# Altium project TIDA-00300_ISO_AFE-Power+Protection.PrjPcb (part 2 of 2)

## Sheet TIDA-00300_ISO_AFE-Power+Protection _Pg5.SchDoc: ISOLATED AFE SUPPLY , LDOs
size 431 x 279 mm; Date: Not shown in title block; ApprovedBy: Not shown in title block; CheckedBy: Not shown in title block; Author: Not shown in title block; CompanyName: Not shown in title block; DrawnBy: Sreenivasa; Engineer: Not shown in title block; Organization: Not shown in title block; Address1: Not shown in title block; Address2: Not shown in title block; Address3: Not shown in title block; Address4: Not shown in title block; DocumentNumber: 1; Revision: Use project parameter SCH_Rev; SheetNumber: 5; SheetTotal: 6; PageSetup: Record=PageOptions¦CenterHorizontal=True¦CenterVertical=True¦PrintScale=0.62¦XCorrection=1.00¦YCorrection=1.00¦PrintKind=0¦BorderSize=5000000¦LeftOffset=0¦BottomOffset=0¦Orientation=2¦PaperLength=1000¦PaperWidth=1000¦Scale=100¦PaperSource=15¦PrintQuality=600¦MediaType=1¦DitherType=10¦PrintScaleMode=1¦PaperKind=Letter
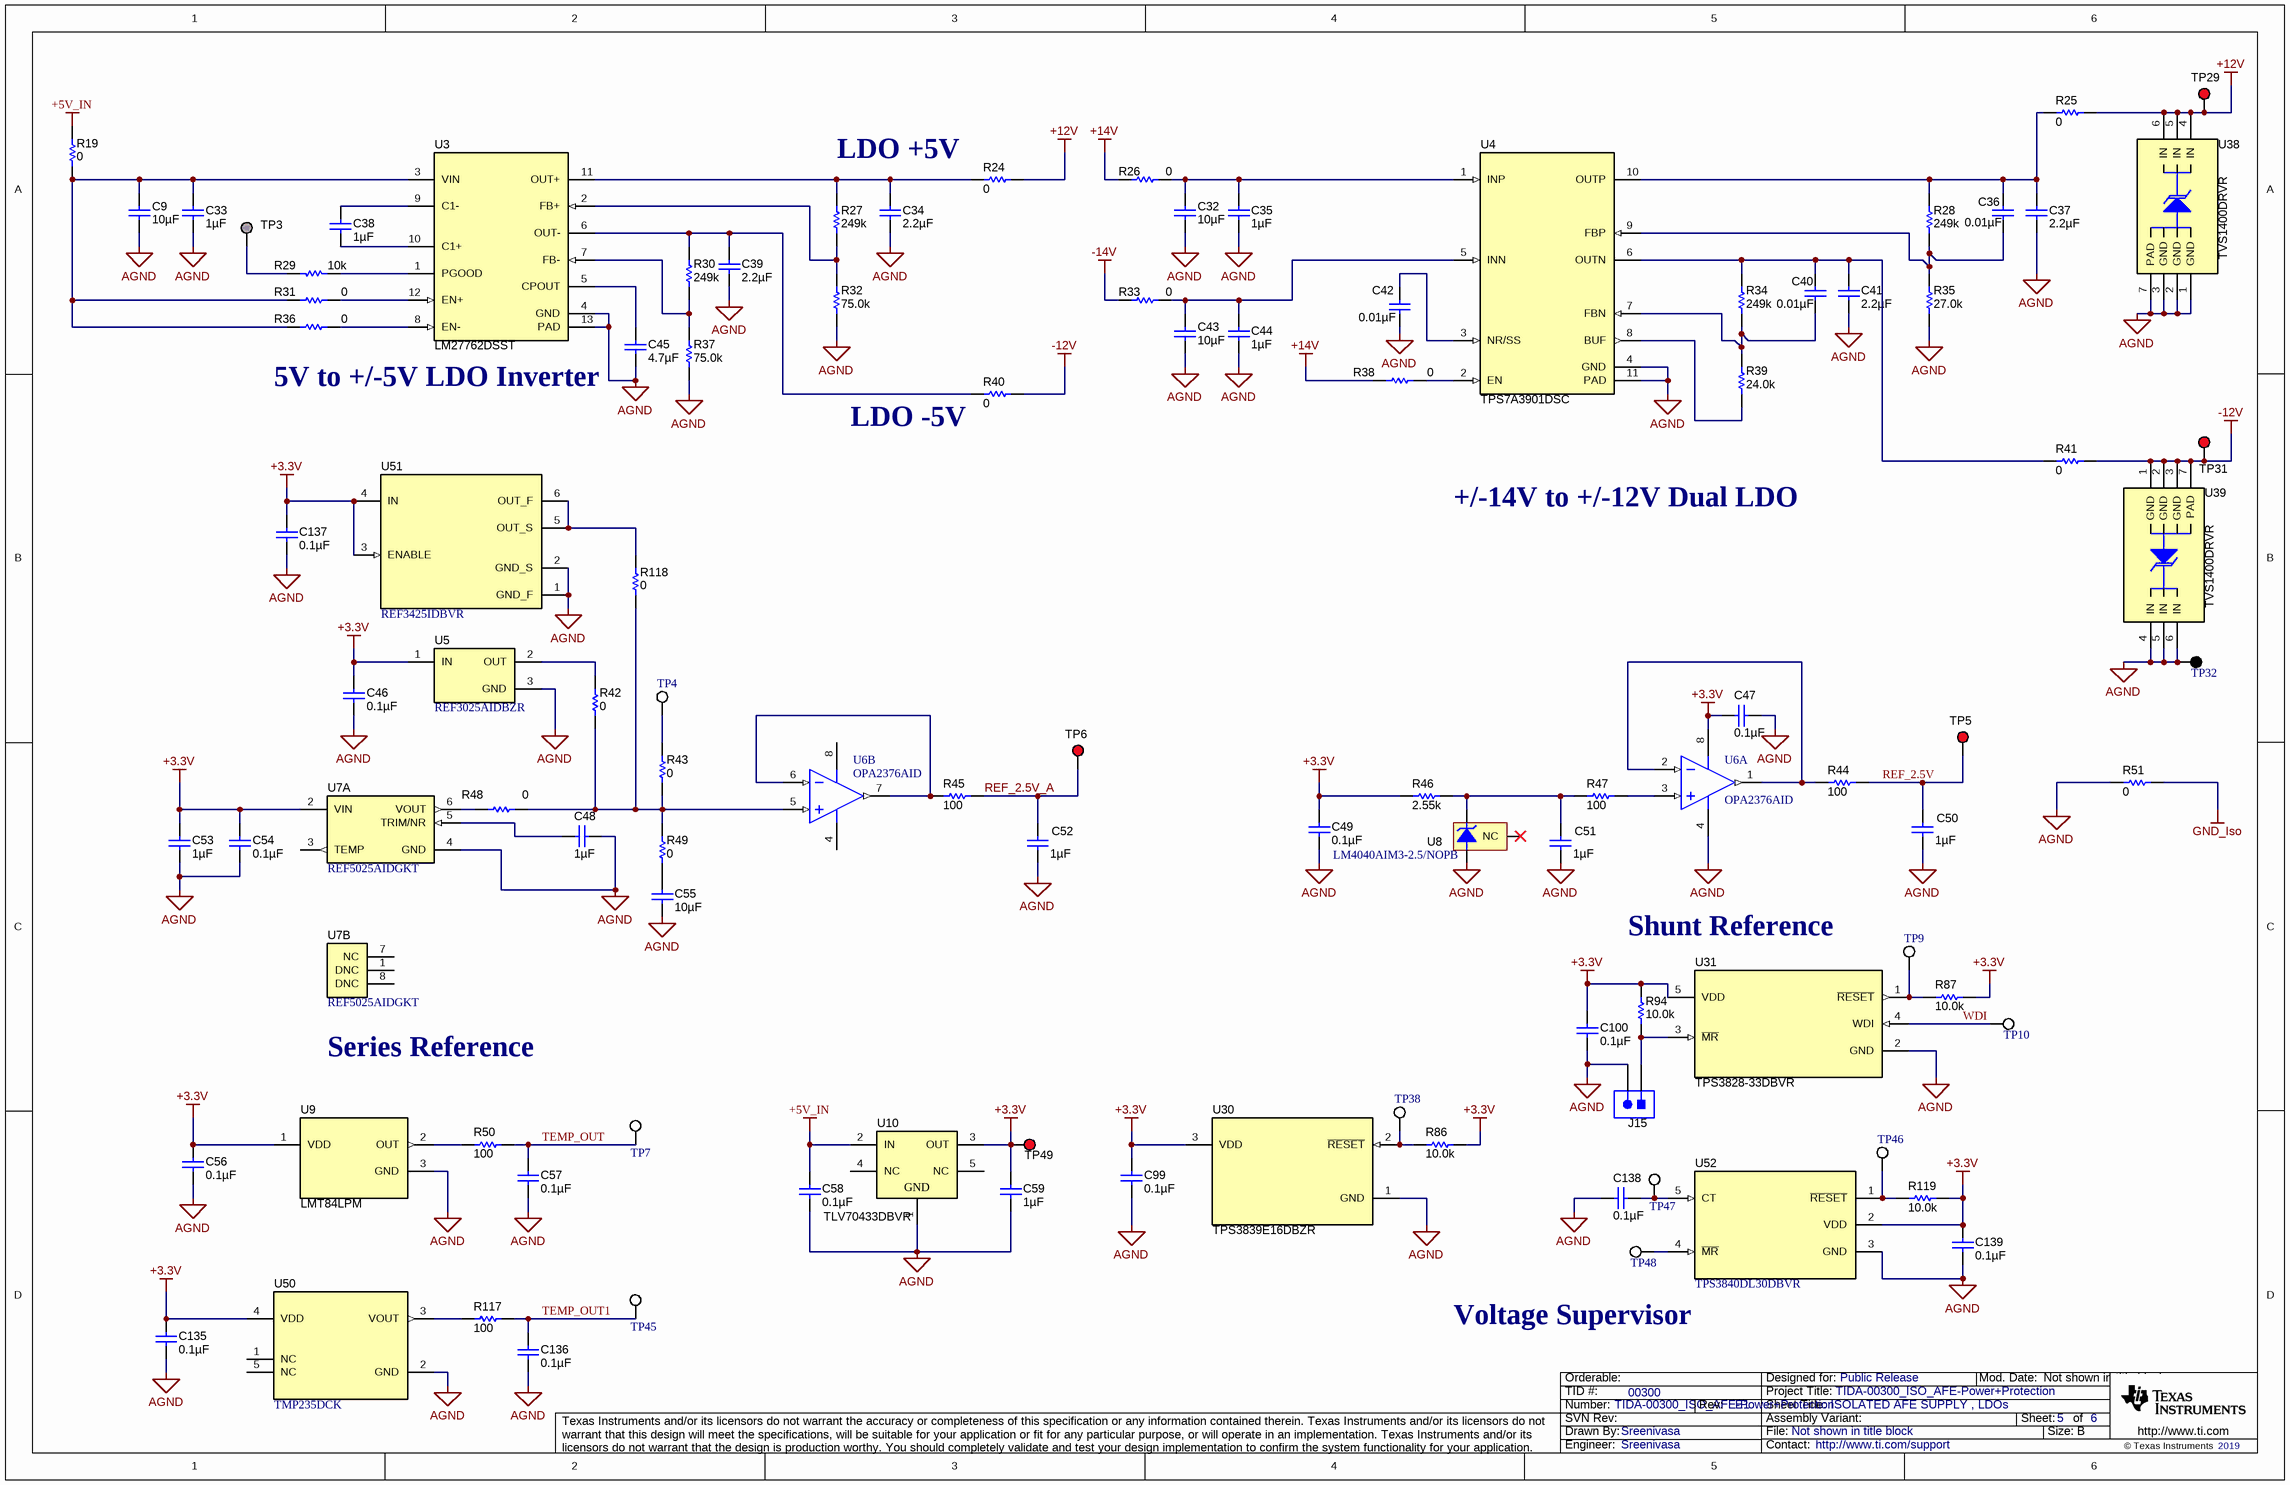
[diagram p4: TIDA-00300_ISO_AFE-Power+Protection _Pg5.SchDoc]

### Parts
C9  ValueDisplayed: 10µF  [1210]
C32  ValueDisplayed: 10µF  [1210]
C33  ValueDisplayed: 1µF  [0603S]  (hidden comment: CGA3E1X7R1E105K080AC)
C34  ValueDisplayed: 2.2µF  [0805_HV]  (hidden comment: C0805C225K8RACTU)
C35  ValueDisplayed: 1µF  [0603S]  (hidden comment: CGA3E1X7R1E105K080AC)
C36  ValueDisplayed: 0.01µF  [0603]  (hidden comment: 885012206040)
C37  ValueDisplayed: 2.2µF  [0805_HV]  (hidden comment: C0805C225K8RACTU)
C38  ValueDisplayed: 1µF  [0603S]  (hidden comment: CGA3E1X7R1E105K080AC)
C39  ValueDisplayed: 2.2µF  [0805_HV]  (hidden comment: C0805C225K8RACTU)
C40  ValueDisplayed: 0.01µF  [0603]  (hidden comment: 885012206040)
C41  ValueDisplayed: 2.2µF  [0805_HV]  (hidden comment: C0805C225K8RACTU)
C42  ValueDisplayed: 0.01µF  [0603]  (hidden comment: 885012206040)
C43  ValueDisplayed: 10µF  [1210]
C44  ValueDisplayed: 1µF  [0603S]  (hidden comment: CGA3E1X7R1E105K080AC)
C45  ValueDisplayed: 4.7µF  [1206]  (hidden comment: C3216X7R1E475M160AC)
C46  ValueDisplayed: 0.1µF  [0603]  (hidden comment: 06033D104KAT2A)
C47  ValueDisplayed: 0.1µF  [0603]  (hidden comment: 06033D104KAT2A)
C48  ValueDisplayed: 1µF  [0805_HV]  (hidden comment: CL21B105KPFNNNE)
C49  ValueDisplayed: 0.1µF  [0603]  (hidden comment: 06033D104KAT2A)
C50  ValueDisplayed: 1µF  [0805_HV]  (hidden comment: C2012X7R1H105K125AE)
C51  ValueDisplayed: 1µF  [0805_HV]  (hidden comment: C2012X7R1H105K125AE)
C52  ValueDisplayed: 1µF  [0805_HV]  (hidden comment: C2012X7R1H105K125AE)
C53  ValueDisplayed: 1µF  [0805_HV]  (hidden comment: CL21B105KPFNNNE)
C54  ValueDisplayed: 0.1µF  [0603]  (hidden comment: 06033D104KAT2A)
C55  ValueDisplayed: 10µF  [0603]  (hidden comment: EMK107BBJ106MA-T)
C56  ValueDisplayed: 0.1µF  [0603]  (hidden comment: 06033D104KAT2A)
C57  ValueDisplayed: 0.1µF  [0603]  (hidden comment: 06033D104KAT2A)
C58  ValueDisplayed: 0.1µF  [0603]  (hidden comment: 06033D104KAT2A)
C59  ValueDisplayed: 1µF  [0603]  (hidden comment: CGB3B3X7R0J105K055AB)
C99  ValueDisplayed: 0.1µF  [0603]  (hidden comment: 06033D104KAT2A)
C100  ValueDisplayed: 0.1µF  [0603]  (hidden comment: 06033D104KAT2A)
C135  ValueDisplayed: 0.1µF  [0603]  (hidden comment: 06033D104KAT2A)
C136  ValueDisplayed: 0.1µF  [0603]  (hidden comment: 06033D104KAT2A)
C137  ValueDisplayed: 0.1µF  [0603]  (hidden comment: 06033D104KAT2A)
C138  ValueDisplayed: 0.1µF  [0603]  (hidden comment: 06033D104KAT2A)
C139  ValueDisplayed: 0.1µF  [0603]  (hidden comment: 06033D104KAT2A)
J15  PBC02SAAN  [Sullins_PBC02SAAN]  (value not drawn)
R19  ValueDisplayed: 0  [1206]  (hidden comment: CRCW12060000Z0EA)
R24  ValueDisplayed: 0  [0603]  (hidden comment: CRCW06030000Z0EA)
R25  ValueDisplayed: 0  [0603]  (hidden comment: CRCW06030000Z0EA)
R26  ValueDisplayed: 0  [0603]  (hidden comment: CRCW06030000Z0EA)
R27  ValueDisplayed: 249k  [0603]  (hidden comment: CRCW0603249KFKEA)
R28  ValueDisplayed: 249k  [0603]  (hidden comment: CRCW0603249KFKEA)
R29  value 10k  [0603]  (hidden comment: CRCW060310K0FKEA)
R30  ValueDisplayed: 249k  [0603]  (hidden comment: CRCW0603249KFKEA)
R31  ValueDisplayed: 0  [0603]  (hidden comment: CRCW06030000Z0EA)
R32  ValueDisplayed: 75.0k  [0603]  (hidden comment: CRCW060375K0FKEA)
R33  ValueDisplayed: 0  [0603]  (hidden comment: CRCW06030000Z0EA)
R34  ValueDisplayed: 249k  [0603]  (hidden comment: CRCW0603249KFKEA)
R35  ValueDisplayed: 27.0k  [0603]  (hidden comment: RC0603FR-0727KL)
R36  ValueDisplayed: 0  [0603]  (hidden comment: CRCW06030000Z0EA)
R37  ValueDisplayed: 75.0k  [0603]  (hidden comment: CRCW060375K0FKEA)
R38  ValueDisplayed: 0  [0603]  (hidden comment: CRCW06030000Z0EA)
R39  ValueDisplayed: 24.0k  [0603]  (hidden comment: RC0603FR-0724KL)
R40  ValueDisplayed: 0  [0603]  (hidden comment: CRCW06030000Z0EA)
R41  ValueDisplayed: 0  [0603]  (hidden comment: CRCW06030000Z0EA)
R42  value 0  [0603]  (hidden comment: CRCW06030000Z0EA)
R43  value 0  [0603]  (hidden comment: CRCW06030000Z0EA)
R44  ValueDisplayed: 100  [0603]  (hidden comment: CRCW0603100RFKEA)
R45  ValueDisplayed: 100  [0603]  (hidden comment: CRCW0603100RFKEA)
R46  ValueDisplayed: 2.55k  [0603]  (hidden comment: CRCW06032K55FKEA)
R47  ValueDisplayed: 100  [0603]  (hidden comment: CRCW0603100RFKEA)
R48  value 0  [0603]  (hidden comment: CRCW06030000Z0EA)
R49  value 0  [0603]  (hidden comment: CRCW06030000Z0EA)
R50  ValueDisplayed: 100  [0603]  (hidden comment: CRCW0603100RFKEA)
R51  ValueDisplayed: 0  [1206]  (hidden comment: RC1206JR-070RL)
R86  ValueDisplayed: 10.0k  [0603]  (hidden comment: RC0603FR-0710KL)
R87  ValueDisplayed: 10.0k  [0603]  (hidden comment: RC0603FR-0710KL)
R94  ValueDisplayed: 10.0k  [0603]  (hidden comment: RC0603FR-0710KL)
R117  ValueDisplayed: 100  [0603]  (hidden comment: CRCW0603100RFKEA)
R118  value 0  [0603]  (hidden comment: CRCW06030000Z0EA)
R119  ValueDisplayed: 10.0k  [0603]  (hidden comment: RC0603FR-0710KL)
TP3  Pogo Pad  [PogoPad]  (value not drawn)  (no BOM)
TP4  5002  [Keystone5002]  (value not drawn)
TP5  5000  [Keystone5000]  (value not drawn)
TP6  5000  [Keystone5000]  (value not drawn)
TP7  5002  [Keystone5002]  (value not drawn)
TP9  5002  [Keystone5002]  (value not drawn)
TP10  5002  [Keystone5002]  (value not drawn)
TP29  5000  [Keystone5000]  (value not drawn)
TP31  5000  [Keystone5000]  (value not drawn)
TP32  5001  [Keystone5001]  (value not drawn)
TP38  5002  [Keystone5002]  (value not drawn)
TP45  5002  [Keystone5002]  (value not drawn)
TP46  5002  [Keystone5002]  (value not drawn)
TP47  5002  [Keystone5002]  (value not drawn)
TP48  5002  [Keystone5002]  (value not drawn)
TP49  5000  [Keystone5000]  (value not drawn)
U3  LM27762DSST  [DSS0012B]
U4  TPS7A3901DSC  [DSC0010J]
U5  REF3025AIDBZR  [DBZ0003A_N]
U6  OPA2376AID  [D0008A_N]  (parts A,B of 2)
U7  REF5025AIDGKT  [DGK0008A_N]  (parts A,B of 2)
U8  LM4040AIM3-2.5/NOPB  [MF03A_N]
U9  LMT84LPM  [LP0003A_straight]
U10  TLV70433DBVR  [DBV0005A_N]
U30  TPS3839E16DBZR  [DBZ0003A_N]
U31  TPS3828-33DBVR  [DBV0005A_N]
U38  TVS1400DRVR  [DRV0006A]
U39  TVS1400DRVR  [DRV0006A]
U50  TMP235DCK  [DCK0005A_N]
U51  REF3425IDBVR  [DBV0006A_N]
U52  TPS3840DL30DBVR  [DBV0005A_N]

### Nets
+3.3V: C46.1 C47.2 C49.2 C53.1 C54.1 C56.2 C59.1 C99.1 C100.1 C135.2 C137.1 C139.1 R46.1 R86.1 R87.1 R94.1 R119.1 TP49.1 U5.1(IN) U6.8(V+) U7.2(VIN) U9.1(VDD) U10.3(OUT) U30.3(VDD) U31.5(VDD) U50.4(VDD) U51.3(ENABLE) U51.4(IN) U52.2(VDD)
+5V_IN: C58.1 R19.2 U10.2(IN)
+12V: R24.2 R25.2 TP29.1 U38.4(IN) U38.5(IN) U38.6(IN)
+14V: R26.1 R38.1
-12V: R40.2 R41.2 TP31.1 U39.1(GND) U39.2(GND) U39.3(GND) U39.7(PAD)
-14V: R33.1
AGND: C9.1 C32.1 C33.2 C34.2 C35.2 C37.2 C39.2 C41.2 C42.2 C43.1 C44.2 C45.2 C46.2 C47.1 C48.2 C49.1 C50.2 C51.2 C52.2 C53.2 C54.2 C55.2 C56.1 C57.1 C58.2 C59.2 C99.2 C100.2 C135.1 C136.1 C137.2 C138.1 C139.2 J15.2 R32.1 R35.1 R37.1 R51.1 TP32.1 U3.4(GND) U3.13(PAD) U4.4(GND) U4.11(PAD) U5.3(GND) U6.4(V-) U7.4(GND) U8.2(-V) U9.3(GND) U10.1(GND) U30.1(GND) U31.2(GND) U38.1(GND) U38.2(GND) U38.3(GND) U38.7(PAD) U39.4(IN) U39.5(IN) U39.6(IN) U50.2(GND) U51.1(GND_F) U51.2(GND_S) U52.3(GND)
GND_Iso: R51.2
REF_2.5V: C50.1 R44.2 TP5.1
REF_2.5V_A: C52.1 R45.2 TP6.1
TEMP_OUT: C57.2 R50.2 TP7.1
TEMP_OUT1: C136.2 R117.2 TP45.1
WDI: TP10.1 U31.4(WDI)
NetC9_2: C9.2 C33.1 R19.1 R31.1 R36.1 U3.3(VIN)
NetC32_2: C32.2 C35.1 R26.2 U4.1(INP)
NetC34_1: C34.1 R24.1 R27.2 U3.11(OUT+)
NetC36_1: C36.1 C37.1 R25.1 R28.2 U4.10(OUTP)
NetC36_2: C36.2 R28.1 R35.2 U4.9(FBP)
NetC38_1: C38.1 U3.9(C1-)
NetC38_2: C38.2 U3.10(C1+)
NetC39_1: C39.1 R30.2 R40.1 U3.6(OUT-)
NetC40_1: C40.1 C41.1 R34.2 R41.1 U4.6(OUTN)
NetC40_2: C40.2 R34.1 R39.2 U4.7(FBN)
NetC42_1: C42.1 U4.3(NR/SS)
NetC43_2: C43.2 C44.1 R33.2 U4.5(INN)
NetC45_1: C45.1 U3.5(CPOUT)
NetC48_1: C48.1 U7.5(TRIM/NR)
NetC51_1: C51.1 R46.2 R47.1 U8.1(+V)
NetC55_1: C55.1 R49.2
NetC138_2: C138.2 TP47.1 U52.5(CT)
NetJ15_1: J15.1 R94.2 U31.3(~{MR})
NetR27_1: R27.1 R32.2 U3.2(FB+)
NetR29_1: R29.1 TP3.1
NetR29_2: R29.2 U3.1(PGOOD)
NetR30_1: R30.1 R37.2 U3.7(FB-)
NetR31_2: R31.2 U3.12(EN+)
NetR36_2: R36.2 U3.8(EN-)
NetR38_2: R38.2 U4.2(EN)
NetR39_1: R39.1 U4.8(BUF)
NetR42_1: R42.1 U5.2(OUT)
NetR42_2: R42.2 R43.2 R48.2 R49.1 R118.2 U6.5(IN_B+)
NetR43_1: R43.1 TP4.1
NetR44_1: R44.1 U6.1(OUT_A) U6.2(IN_A-)
NetR45_1: R45.1 U6.6(IN_B-) U6.7(OUT_B)
NetR47_2: R47.2 U6.3(IN_A+)
NetR48_1: R48.1 U7.6(VOUT)
NetR50_1: R50.1 U9.2(OUT)
NetR86_2: R86.2 TP38.1 U30.2(~{RESET})
NetR87_2: R87.2 TP9.1 U31.1(~{RESET})
NetR117_1: R117.1 U50.3(VOUT)
NetR118_1: R118.1 U51.5(OUT_S) U51.6(OUT_F)
NetR119_2: R119.2 TP46.1 U52.1(~{RESET})
NetTP48_1: TP48.1 U52.4(~{MR})

Not connected (* = marked no-connect by the designer): U7 1(DNC) 3(TEMP) 7(NC) 8(DNC); U8 3(NC)*; U10 4(NC) 5(NC); U50 1(NC) 5(NC)

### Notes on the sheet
- LDO +5V
- (near C45) 5V to +/-5V LDO Inverter
- (near R40) LDO -5V
- +/-14V to +/-12V Dual LDO
- Shunt Reference
- (near U7) Series Reference
- Voltage Supervisor

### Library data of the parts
C9 C32 C43 = GMK325AB7106MM-T: CAP, CERM, 10µF ±10% 35V Ceramic Capacitor X7R 1210; PartNumber: GMJ325KB7106KMHP; Manufacturer: Taiyo Yuden; Polarized: N; Value: 10uF; U/M: EA; Cap_F: 0.00001; Tolerance_%: 20; Value1: Unknown; VDC_V: 35; TaMin_C: -55; TaMax_C: 125
C33 C35 C38 C44 = GRM188R71E105KA12D: CAP, CERM, 1 µF, 25 V, +/- 10%, X7R, 0603; Manufacturer: TDK Corporation; Polarized: N; CompType: Capacitor; Value: 1uF; U/M: EA; Cap_F: 0.000001; Tolerance_%: 10; Value1: Unknown; VDC_V: 25; Value2: 25V; TaMin_C: -55; TaMax_C: 125; Cap_Case: 0603; AEC Category: Q200
C34 C37 C39 C41 = C0805C225K8RACTU: CAP, CERM, 2.2uF, 10V, +/-10%, X7R, 0805; Manufacturer: Kemet; Polarized: N; CompType: Capacitor; U/M: EA; Cap_F: 0.0000022; Tolerance_%: 10; ESR_Ohm: 0.008; Value1: 0.008 ohm; IRMS_A: 15.55; TaMin_C: -55; TaMax_C: 125; Cap_Case: 0805
C36 C40 C42 = 885012206040: CAP, CERM, 0.01 µF, 16 V,+/- 10%, X7R, 0603; Manufacturer: Wurth Elektronik; Polarized: N; CompType: Capacitor; Value: 0.01uF; U/M: EA; Cap_F: 0.00000001; Tolerance_%: 10; VDC_V: 16; Value2: 16V; TaMin_C: -55; TaMax_C: 125; SizeArea_mm2: 1.28; SizeAreaWB_mm2: 4.68; SizeX_mm: 1.6; SizeY_mm: 0.8; SizeZ_mm: 1; AEC Category: Q200; Green_Lifecycle: Active; Green_REACh: Passed
C45 = C3216X7R1E475M: CAP, CERM, 4.7 µF, 25 V, +/- 20%, X7R, 1206; Manufacturer: TDK; Polarized: N; CompType: Capacitor; Value: 4.7uF; U/M: EA; Cap_F: 0.0000047; Tolerance_%: 20; ESR_ohm: 0.0063; Value1: 0.0063 ohm; VDC_V: 25; Value2: 25V; TaMin_C: -55; TaMax_C: 125
C46 C54 C58 C99 C100 C137-C139 = 06033D104KAT2A: CAP, CERM, 0.1 µF, 25 V,+/- 10%, X5R, 0603; Manufacturer: AVX; Polarized: N; CompType: Capacitor; Value: 0.1uF; U/M: EA; Cap_F: 0.0000001; Tolerance_%: 10; ESR_ohm: 0.048; Value1: 0.048 ohm; VDC_V: 25; Value2: 25V; IRMS_A: 0.53; TaMin_C: -55; TaMax_C: 85; SizeArea_mm2: 1.28; SizeAreaWB_mm2: 4.68; SizeX_mm: 1.6; SizeY_mm: 0.8; SizeZ_mm: 1; AEC Category: Q200; Green_Lifecycle: Active; Green_REACh: Passed
C47 C49 C56 C57 C135 C136 = 06033D104KAT2A: CAP, CERM, 0.1 µF, 25 V,+/- 10%, X5R, 0603; Manufacturer: AVX; Polarized: N; CompType: Capacitor; Value: 0.1uF; U/M: EA; Cap_F: 0.0000001; Tolerance_%: 10; ESR_ohm: 0.048; Value1: 0.048 ohm; VDC_V: 25; Value2: 25V; IRMS_A: 0.53; TaMin_C: -55; TaMax_C: 85; AEC Category: Q200; SizeArea_mm2: 1.28; SizeAreaWB_mm2: 4.68; SizeX_mm: 1.6; SizeY_mm: 0.8; SizeZ_mm: 1; Green_Lifecycle: Active; Green_REACh: Passed
C48 C53 = C0805C105K8RACTU: CAP, CERM, 1uF, 10V, +/-10%, X7R, 0805; Manufacturer: Samsung Electro-Mechanics; Polarized: N; CompType: Capacitor; U/M: EA; Cap_F: 0.000001; Tolerance_%: 10; ESR_Ohm: 0.015; Value1: 0.015 ohm; IRMS_A: 8.19; TaMin_C: -55; TaMax_C: 125; Cap_Case: 0805
C50-C52 = GRM21BR71H105KA12L: CAP, CERM, 1 µF, 50 V, +/- 10%, X7R, 0805; Manufacturer: MuRata; Polarized: N; CompType: Capacitor; Value: 1uF; U/M: EA; Cap_F: 0.000001; Tolerance_%: 10; Value1: Unknown; VDC_V: 50; Value2: 50V; TaMin_C: -55; TaMax_C: 125; Cap_Case: 0805; AEC Category: Q200
C55 = EMK107BBJ106MA-T: CAP, CERM, 10uF, 16V, +/-20%, X5R, 0603; Manufacturer: Taiyo Yuden; Polarized: N; CompType: Capacitor; U/M: EA; Cap_F: 0.00001; Tolerance_%: 20; Value1: Unknown; VDC_V: 16; TaMin_C: -55; TaMax_C: 85
C59 = CL10B105KQ8NNNC: CAP, CERM, 1 µF, 6.3 V, +/- 10%, X7R, 0603; Manufacturer: TDK Corporation; Polarized: N; CompType: Capacitor; Value: 1uF; U/M: EA; Cap_F: 0.000001; Tolerance_%: 10; Value1: Unknown; VDC_V: 6.3; Value2: 6.3V; TaMin_C: -55; TaMax_C: 125; SizeArea_mm2: 1.28; SizeAreaWB_mm2: 4.68; SizeX_mm: 1.6; SizeY_mm: 0.8; SizeZ_mm: 1; AEC Category: Q200
J15 = PBC02SAAN: Header, 100mil, 2x1, Gold, TH; Manufacturer: Sullins Connector Solutions; SymbolCreator: a0412235; Pitch_mm: 2.54; Gender: Male; Shrouded: N; Row_Count: 1; Current_A: 3; Voltage_V: 1800; Cert_UL: Y
R19 = CRCW12060000Z0EA: RES, 0, 5%, 0.25 W, 1206; Manufacturer: Vishay-Dale; CompType: Resistor; Value: 0; Value_Code: 0000; Tolerance_%: 5; Power_W: 0.25; Value2: 0.25W; VDC_V: 200; TempCo: 200 ppm/C; SizeArea_mm2: 5.12; SizeX_mm: 3.2; SizeY_mm: 1.6; SizeZ_mm: 1.35; EIA_Code: E24; U/M: EA; AEC Category: Q200
R24-R26 R31 R33 R36 R38 R40 R41 = CRCW06030000Z0EA: RES, 0, 5%, 0.1 W, 0603; Manufacturer: Vishay-Dale; CompType: Resistor; Value: 0; Value_Code: 0000; Tolerance_%: 5; Power_W: 0.1; Value2: 0.1W; VDC_V: 75; TempCo: 200 ppm/C; EIA_Code: E24; U/M: EA
R27 R28 R30 R34 = CRCW0603249KFKEA: RES, 249 k, 1%, 0.1 W, 0603; Manufacturer: Vishay-Dale; CompType: Resistor; Value: 249k; Res_ohm: 249000; Tolerance_%: 1; Power_W: 0.1; Value2: 0.1W; VDC_V: 75; TempCo: 100 ppm/C; SizeArea_mm2: 1.28; SizeX_mm: 1.6; SizeY_mm: 0.8; EIA_Code: E96; U/M: EA; AEC Category: Q200
R29 = RNCF0603TKY10K0: RES, 10.0k ohm, 1%, 0.1W, 0603; Manufacturer: Stackpole Electronics Inc; CompType: Resistor; Res_ohm: 10000; Value_Code: 10k0; Tolerance_%: 0.01; Value1: 0.01%; Power_W: 0.063; Value2: 0.063W; VDC_V: 50; TempCo: 5 ppm/C; U/M: EA
R32 R37 = CRCW060375K0FKEA: RES, 75.0 k, 1%, 0.1 W, 0603; Manufacturer: Vishay-Dale; CompType: Resistor; Value: 75.0k; Res_ohm: 75000; Value_Code: 75k0; Tolerance_%: 1; Power_W: 0.1; Value2: 0.1W; VDC_V: 75; TempCo: 100 ppm/C; SizeArea_mm2: 1.28; SizeX_mm: 1.6; SizeY_mm: 0.8; EIA_Code: E96; U/M: EA; AEC Category: Q200
R35 = RC0603FR-0727KL: RES, 27.0 k, 1%, 0.1 W, 0603; Manufacturer: Yageo America; CompType: Resistor; Value: 27.0k; Res_ohm: 27000; Value_Code: 27k0; Tolerance_%: 1; Power_W: 0.1; Value2: 0.1W; VDC_V: 150; TempCo: 200 ppm/C; SizeArea_mm2: 1.28; SizeX_mm: 1.6; SizeY_mm: 0.8; U/M: EA; AEC Category: Q200; Green_Lifecycle: Active; Green_REACh: Passed
R39 = RC0603FR-0724KL: RES, 24.0 k, 1%, 0.1 W, 0603; Manufacturer: Yageo America; CompType: Resistor; Value: 24.0k; Res_ohm: 24000; Value_Code: 24k0; Tolerance_%: 1; Power_W: 0.1; Value2: 0.1W; VDC_V: 150; TempCo: 200 ppm/C; SizeArea_mm2: 1.28; SizeX_mm: 1.6; SizeY_mm: 0.8; U/M: EA; AEC Category: Q200; Green_Lifecycle: Active; Green_REACh: Passed
R42 R43 R48 R49 R118 = CRCW06030000Z0EA: RES, 0 ohm, 5%, 0.1W, 0603; Manufacturer: Vishay-Dale; CompType: Resistor; Value_Code: 0000; Tolerance_%: 5; Power_W: 0.1; VDC_V: 75; TempCo: 200 ppm/C; EIA_Code: E24; U/M: EA
R44 R45 R47 R50 R117 = CRCW0603100RFKEA: RES, 100, 1%, 0.1 W, 0603; Manufacturer: Vishay-Dale; CompType: Resistor; Value: 100; Value_Code: 100R; Tolerance_%: 1; Power_W: 0.1; Value2: 0.1W; VDC_V: 75; TempCo: 100 ppm/C; EIA_Code: E96; U/M: EA; AEC Category: Q200
R46 = CRCW06032K55FKEA: RES, 2.55 k, 1%, 0.1 W, 0603; Manufacturer: Vishay-Dale; CompType: Resistor; Value: 2.55k; Res_ohm: 2550; Value_Code: 2k55; Tolerance_%: 1; Power_W: 0.1; Value2: 0.1W; VDC_V: 75; TempCo: 100 ppm/C; EIA_Code: E96; U/M: EA; AEC Category: Q200
R51 = RC1206JR-070RL: RES, 0, 5%, 0.25 W, 1206; Manufacturer: Yageo America; CompType: Resistor; Value: 0; Value_Code: 0000; Tolerance_%: 5; Power_W: 0.25; Value2: 0.25W; VDC_V: 200; TempCo: 200 ppm/C; SizeArea_mm2: 5.12; SizeX_mm: 3.2; SizeY_mm: 1.6; SizeZ_mm: 1.35; EIA_Code: E24; U/M: EA; AEC Category: Q200; Green_Lifecycle: Active; Green_REACh: Passed
R86 R87 R94 R119 = RC0603FR-0710KL: RES, 10.0 k, 1%, 0.1 W, 0603; Manufacturer: Yageo America; CompType: Resistor; Value: 10.0k; Res_ohm: 10000; Value_Code: 10k0; Tolerance_%: 1; Power_W: 0.1; Value2: 0.1W; VDC_V: 150; TempCo: 200 ppm/C; SizeArea_mm2: 1.28; SizeX_mm: 1.6; SizeY_mm: 0.8; EIA_Code: E96; U/M: EA; AEC Category: Q200; Green_Lifecycle: Active; Green_REACh: Passed
TP3 = PogoPad: Pad for Pogo Pin Connector; SymbolCreator: codlsc
TP4 TP7 TP9 TP10 TP38 TP45-TP48 = 5002: Test Point, Miniature, White, TH; Manufacturer: Keystone; CompType: Test Point Loop; ContactFinish: Silver; Green_Lifecycle: Active; Green_REACh: Passed
TP5 TP6 TP29 TP31 TP49 = 5000: Test Point, Miniature, Red, TH; Manufacturer: Keystone; CompType: Test Point Loop; ContactFinish: Silver
TP32 = 5001: Test Point, Miniature, Black, TH; Manufacturer: Keystone; CompType: Test Point Loop; ContactFinish: Silver; Green_Lifecycle: Active; Green_REACh: Passed
U3 = LM27762DSSR: Low-Noise Regulated Switched-Capacitor Voltage Inverter and Positive LDO, DSS0012B; Manufacturer: Texas Instruments; SymbolCreator: Altium; SizeArea_mm2: 6; SizeAreaWB_mm2: 12; SizeX_mm: 2; SizeY_mm: 3; SizeZ_mm: 0.8; CompType: IC; U/M: EA
U4 = TPS7A3901DSC: Wide-VIN (±33 V), 150-mA, Spilt-Rail Output, Positive and Negative LDO Voltage Regulator with Startup Tracking, DSC0010J; Manufacturer: Texas Instruments; SymbolCreator: Altium; SizeArea_mm2: 9; SizeAreaWB_mm2: 16; SizeX_mm: 3; SizeZ_mm: 0.8; CompType: IC; U/M: EA
U5 = REF3025AIDBZR: 2.5 V, 50 ppm / degC, 50 uA Series (Bandgap) Voltage Reference, -40 to 125 degC, 3-pin SOT-23 (DBZ), Green (RoHS & no Sb/Br); Manufacturer: Texas Instruments; Alternate PartNumber: Equivalent; Initial Accuracy @ 25/deg C(%): 0.2; Iq(Max)(uA): 50; Rating: Catalog; SubFamily: Series Voltage Reference; Temp Coeff(Typ)(ppm/ degree C): 20; VI(Max)(V): 5.5; VI(Min)(V): 2.501; VO(V): 2.5
U6 = CMP-0040811-1: Precision, Low Noise, Low Quiescent Current Operational Amplifier, 2 to 5.5 V, -40 to 125 degC, 8-pin SOIC (D8), Green (RoHS & no Sb/Br); Manufacturer: Texas Instruments; Total Supply Voltage(Min)(+5V is 5, +/-5V is 10): 2; Vn at 1kHz(Typ)(nV/rtHz): 7.5; CMRR(Min)(dB): 76; Sub Family: Low Input Bias Current Amp (<=10pA), Low Noise Amp (<=10nV/rtHz), Low Offset Voltage Amplifier (<=500uV), Low Supply Voltage Amplifier (<=2.7V), Precision Amplifier; Iq per channel(Max)(mA): 0.95; Total Supply Voltage(Max)(+5V is 5, +/-5V is 10): 5.5; Vio (25C)(Max)(mV): 0.025; IIB(Max)(pA): 10; Offset Drift(Typ)(uV/C): 0.32
U7 = REF5025AIDGKT: Low Noise, Very Low Drift, Precision Voltage Reference, -40 to 125 degC, 8-pin MSOP(DGK), Green (RoHS & no Sb/Br); Manufacturer: Texas Instruments; Alternate PartNumber: Equivalent; Initial Accuracy @ 25/deg C(%): 0.05; Iout/Iz(Max)(mA): 10; Iq(Max)(uA): 1000; Rating: Military; SubFamily: Series Voltage Reference; Temp Coeff(Max)(ppm/ degree C): 3; VI(Max)(V): 18; VI(Min)(V): 2.7; VO(V): 2.5
U8 = LM4040AIM3-2.5/NOPB: Precision Micropower Shunt Voltage Reference, 3-pin SOT-23, Pb-Free; Manufacturer: Texas Instruments; PackageTopMarking: R2A*XTT; PowerWise: N; CompType: Voltage Reference IC
U9 = CMP-0076506-2: 1.5V-Capable, 10 uA Analog Output Temperature Sensor in SC70 and TO-92, LP0003A (TO-92-3); Manufacturer: Texas Instruments; SizeZ_mm: 9.33; SizeX_mm: 3.68; SizeY_mm: 5.0; SizeArea_mm2: 18.4; CompType: IC; U/M: EA; SizeAreaWB_mm2: 39.76
U10 = TLV70433DBVR: Single Output LDO, 150 mA, Fixed 3.3 V Output, 2.5 to 24 V Input, with Ultra-Low IQ, 5-pin SOT-23 (DBV), -40 to 125 degC, Green (RoHS & no Sb/Br); Manufacturer: Texas Instruments; Alternate PartNumber: Equivalent; Accuracy(%): 2; Fixed Output Options(V): 3.3; Iout(Max)(A): 0.15; Iq(Typ)(mA): 0.003; SubFamily: Single Channel LDO; Vdo(Typ)(mV): 400; Vin(Max)(V): 24; Vin(Min)(V): 2.5
U30 = CMP-0074269-1: 150-nA, Ultralow Power, Supply Voltage Monitor, DBZ0003A (SOT-23-3); Alternate PartNumber: TPS3839E16DBZT; Alternate Manufacturer: Texas Instruments; SizeAreaWB_mm2: 14.0; SizeZ_mm: 1.12; SizeX_mm: 2.5; SizeY_mm: 3.0; SizeArea_mm2: 7.5; CompType: IC
U31 = CMP-0067355-1: Voltage Monitor With Watchdog Timer, DBV0005A (SOT-23-5); Alternate PartNumber: TPS3828-33DBVT; Alternate Manufacturer: Texas Instruments; SizeAreaWB_mm2: 14.82; U/M: EA; SizeZ_mm: 1.45; SizeX_mm: 2.8; SizeY_mm: 2.9; SizeArea_mm2: 8.12; CompType: IC
U38 U39 = CMP-0077836-1: 14-V Precision Surge Protection Clamp, DRV0006A (WSON-6); Alternate Manufacturer: Texas Instruments; SizeAreaWB_mm2: 9.0; SizeZ_mm: 0.8; SizeX_mm: 2.0; SizeArea_mm2: 4.0; CompType: IC; AEC Qualified: N; AEC Category: Q200
U50 = CMP-0013250-1: TMP235DCK, DCK0005A (SOT-5); Manufacturer: Texas Instruments; SizeZ_mm: 1.1; SizeX_mm: 2.1; SizeY_mm: 2; SizeArea_mm2: 4.2; CompType: IC; U/M: EA; SizeAreaWB_mm2: 9.3
U51 = CMP-0083672-1: 2.5V Low-Drift Low-Power Small-Footprint Series Voltage Reference, DBV0006A (SOT-23-6); Alternate Manufacturer: Texas Instruments; SizeAreaWB_mm2: 14.82; Rating: Catalog; SizeZ_mm: 1.45; SizeX_mm: 2.8; SizeY_mm: 2.9; SizeArea_mm2: 8.12; CompType: IC; AEC Qualified: N; AEC Category: Q200
U52 = CMP-0084479-1: Nano Power, Wide VIN Voltage Detector with Programmable Delay, DBV0005A (SOT-23-5); Manufacturer: Texas Instruments; SizeZ_mm: 1.45; SizeArea_mm2: 8.12; SizeY_mm: 2.9; AEC Category: Q200; AEC Qualified: N; CompType: IC; SizeAreaWB_mm2: 14.82; SizeX_mm: 2.8

## Sheet TIDA-00300_ISO_AFE-Power+Protection _EVM_Hardware_Pg6.SchDoc: Hardware
size 431 x 279 mm; Date: Not shown in title block; ApprovedBy: Not shown in title block; CheckedBy: Not shown in title block; Author: Not shown in title block; CompanyName: Not shown in title block; DrawnBy: Sreenivasa; Engineer: Not shown in title block; Organization: Not shown in title block; Address1: Not shown in title block; Address2: Not shown in title block; Address3: Not shown in title block; Address4: Not shown in title block; DocumentNumber: 1; Revision: Use project parameter SCH_Rev; SheetNumber: 6; SheetTotal: 6; PageSetup: Record=PageOptions¦CenterHorizontal=True¦CenterVertical=True¦PrintScale=1.00¦XCorrection=1.00¦YCorrection=1.00¦PrintKind=0¦BorderSize=5000000¦LeftOffset=0¦BottomOffset=0¦Orientation=2¦PaperLength=1000¦PaperWidth=1000¦Scale=100¦PaperSource=15¦PrintQuality=600¦MediaType=1¦DitherType=10¦PaperKind=Letter¦PrintScaleMode=1
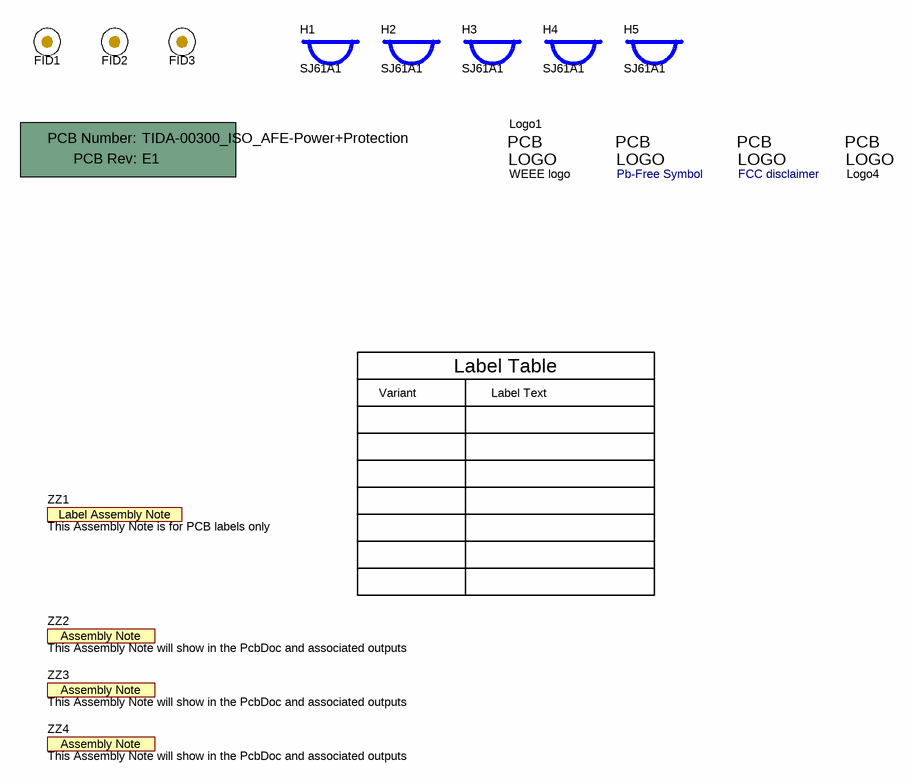
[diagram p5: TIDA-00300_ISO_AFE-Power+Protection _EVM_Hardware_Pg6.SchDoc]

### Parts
!PCB1  Printed Circuit Board  (value not drawn)  (mechanical)
FID1  Fiducial  [Fiducial10-30]  (value not drawn)
FID2  Fiducial  [Fiducial10-30]  (value not drawn)
FID3  Fiducial  [Fiducial10-30]  (value not drawn)
H1  SJ61A1  [Bumpon_SJ61A1]
H2  SJ61A1  [Bumpon_SJ61A1]
H3  SJ61A1  [Bumpon_SJ61A1]
H4  SJ61A1  [Bumpon_SJ61A1]
H5  SJ61A1  [Bumpon_SJ61A1]
Logo1  WEEE logo  [WEEE_Minimum]  (no BOM)
Logo2  Pb-Free Symbol  [Pb-Free_Overlay_Small]  (no BOM)
Logo3  FCC disclaimer  [FCC_disclaimer_stacked]  (no BOM)
Logo4  ESD Susceptible  [ESD_Overlay_Medium]  (value not drawn)  (no BOM)
ZZ1  This Assembly Note is for PCB labels only  [AssemblyNoteLabel]  (no BOM)
ZZ2  This Assembly Note will show in the PcbDoc and associated outputs  [AssemblyNote]  (no BOM)
ZZ3  This Assembly Note will show in the PcbDoc and associated outputs  [AssemblyNote]  (no BOM)
ZZ4  This Assembly Note will show in the PcbDoc and associated outputs  [AssemblyNote]  (no BOM)

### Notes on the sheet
- Variant
- Label Table
- Label Text

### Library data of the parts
!PCB1 = PCB: Manufacturer: Any; PartNumber: TIDA-00300_ISO_AFE-Power+Protection; SymbolCreator: a0412235
FID1-FID3 = Fiducial: Fiducial mark.  There is nothing to buy or mount.; SymbolCreator: codlsc
H1-H5 = SJ61A1: Bumpon, Cylindrical, 0.312 X 0.200, Black; Manufacturer: 3M; SymbolCreator: a0412235; Green_Lifecycle: Not Set; Green_REACh: Incomplete
Logo1 = CMP-0074769-1
Logo2 = Pb-Free: SymbolCreator: a0412235
Logo3 = FCC_disclaimer: SymbolCreator: codlsc
Logo4 = ESD_Susceptible: ESD Susceptible Symbol; SymbolCreator: a0412235
ZZ1 = AssemblyNoteLabel: SymbolCreator: a0412235
ZZ2-ZZ4 = AssemblyNote: SymbolCreator: codlsc

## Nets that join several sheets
+5V_IN: TIDA-00300_ISO_AFE-Power+Protection _Pg3 (R112.2 R113.2 TP44.1), TIDA-00300_ISO_AFE-Power+Protection _Pg4 (L3.1), TIDA-00300_ISO_AFE-Power+Protection _Pg5 (C58.1 R19.2 U10.2)
+14V: TIDA-00300_ISO_AFE-Power+Protection _Pg4 (5 pins), TIDA-00300_ISO_AFE-Power+Protection _Pg5 (R26.1 R38.1)
-14V: TIDA-00300_ISO_AFE-Power+Protection _Pg4 (5 pins), TIDA-00300_ISO_AFE-Power+Protection _Pg5 (R33.1)
GND_Iso: TIDA-00300_ISO_AFE-Power+Protection _Pg3 (21 pins), TIDA-00300_ISO_AFE-Power+Protection _Pg4 (24 pins), TIDA-00300_ISO_AFE-Power+Protection _Pg5 (R51.2)

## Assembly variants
001: not fitted C56 C57 C99 C100 C135 C136 C138 C139 FID1 FID2 FID3 J15 R24 R40 R42 R50 R86 R87 R94 R113 R117 R118 R119 TP7 TP9 TP10 TP38 TP45 TP46 TP47 TP48 U9 U30 U31 U50 U52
